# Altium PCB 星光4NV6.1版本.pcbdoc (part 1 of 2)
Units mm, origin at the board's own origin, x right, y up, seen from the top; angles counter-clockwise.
Board outline 96.4 x 47 mm, 2 copper layers (Top Layer, Bottom Layer), stack 1.58 mm thick; 27 components, 21 nets, 135 pads, 175 vias.
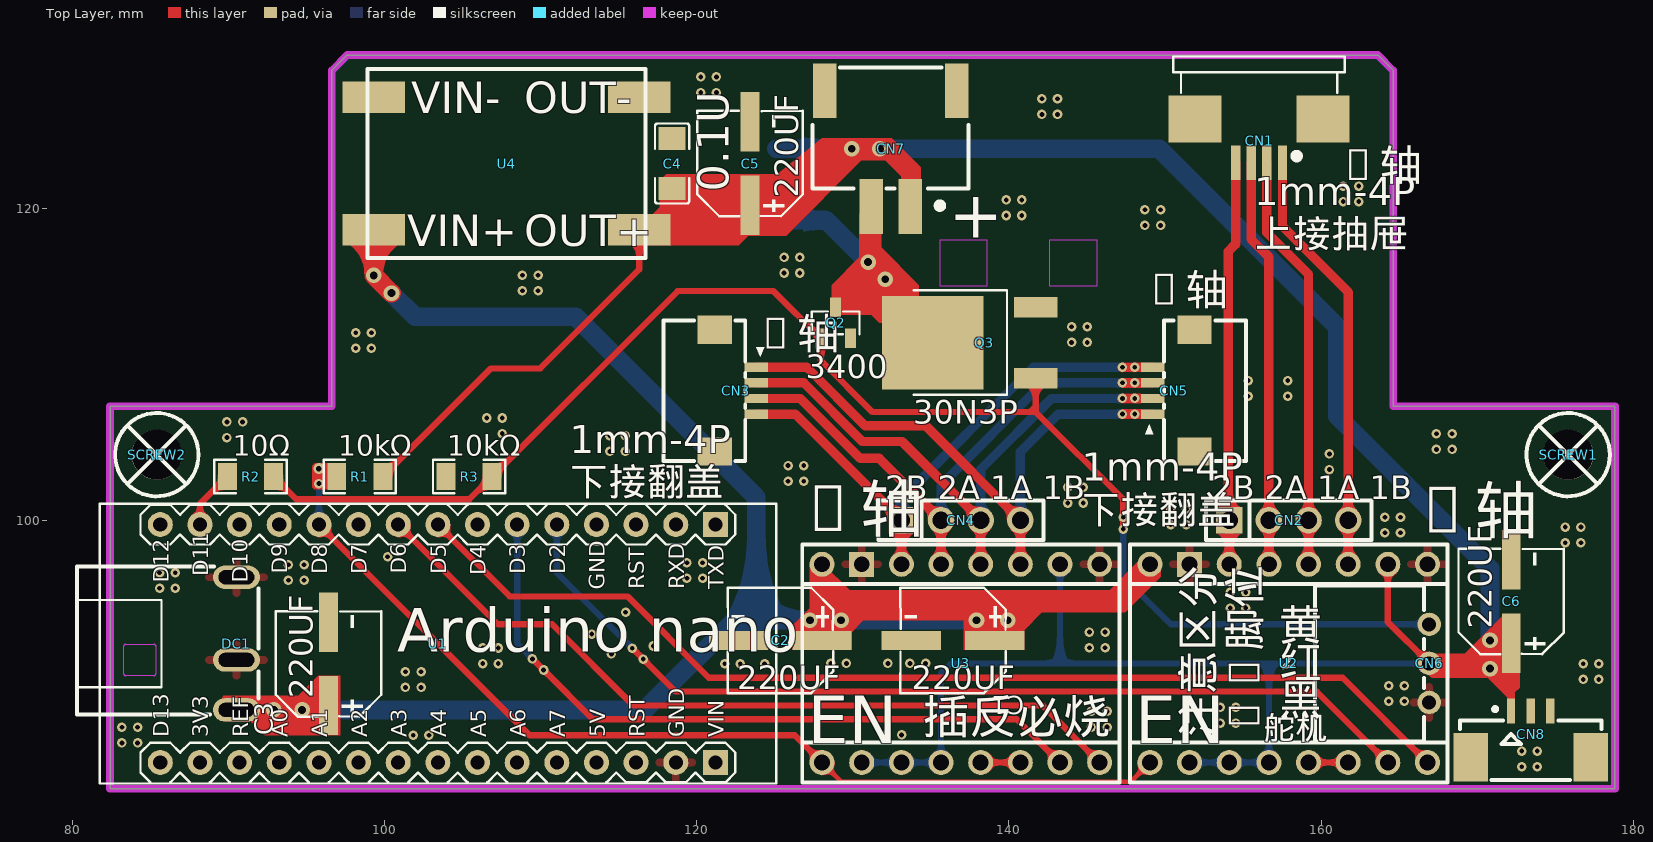
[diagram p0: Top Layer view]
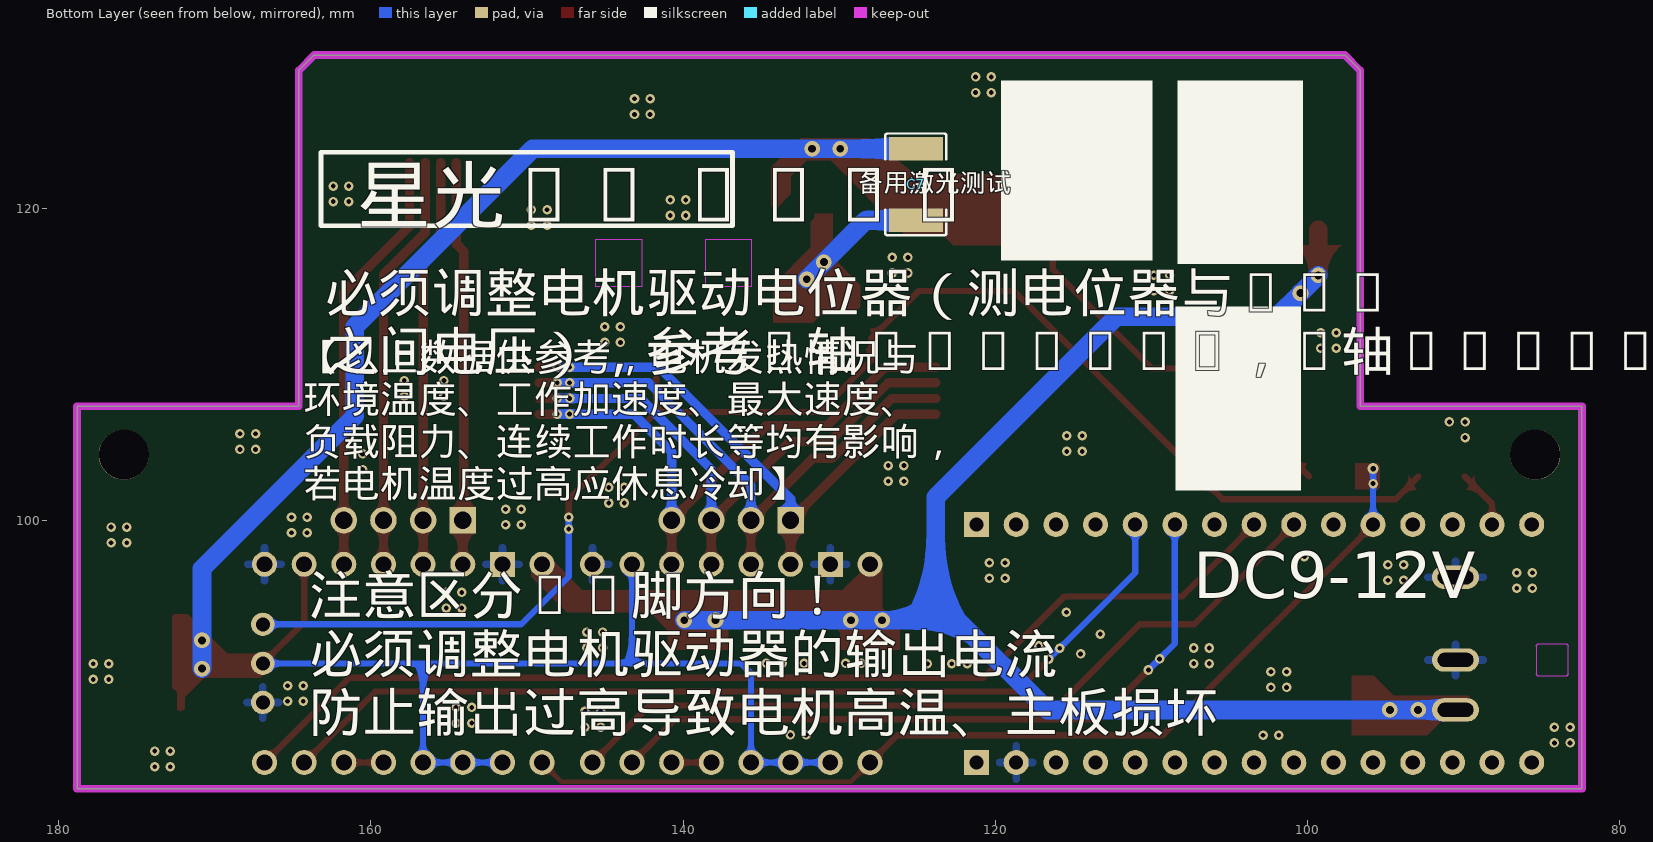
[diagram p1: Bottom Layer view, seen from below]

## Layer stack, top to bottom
Top Solder Mask Layer: solder mask 0.01, Dk 3.3
Top Layer: signal copper 0.035
Dielectric1: surface 1.51, FR4, Dk 4.5
Bottom Layer: signal copper 0.035
Bottom Solder Mask Layer: solder mask 0.01, Dk 3.3

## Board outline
97.623,129.804 163.623,129.804 164.623,128.804 164.623,107.304 164.623,114.304 164.623,107.304 178.823,107.304 178.823,82.804 82.423,82.804 82.423,107.304 96.623,107.304 96.623,128.804

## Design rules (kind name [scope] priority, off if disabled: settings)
BoardOutlineClearance copperThickness1oz [All] p0: genericclearance=0.254 ignorepadtopadclearanceinfootprint=FALSE except(0: Arc-SplitContinuation Track-SplitContinuation SMDPad-SplitContinuation THPad-SplitContinuation Via-SplitContinuation Fill-SplitContinuation Poly-SplitContinuation Region-SplitContinuation Text-SplitContinuation)
BoardOutlineClearance copperThickness2oz [All] p0: genericclearance=0.254 ignorepadtopadclearanceinfootprint=FALSE except(0: Arc-SplitContinuation Track-SplitContinuation SMDPad-SplitContinuation THPad-SplitContinuation Via-SplitContinuation Fill-SplitContinuation Poly-SplitContinuation Region-SplitContinuation Text-SplitContinuation)
BoardOutlineClearance Plane_innerPlane [All] p0: genericclearance=0.254 ignorepadtopadclearanceinfootprint=FALSE except(0: Arc-SplitContinuation Track-SplitContinuation SMDPad-SplitContinuation THPad-SplitContinuation Via-SplitContinuation Fill-SplitContinuation Poly-SplitContinuation Region-SplitContinuation Text-SplitContinuation)
BoardOutlineClearance Copper_copperRegion [All] p0: genericclearance=0.254 ignorepadtopadclearanceinfootprint=FALSE except(0: Arc-SplitContinuation Track-SplitContinuation SMDPad-SplitContinuation THPad-SplitContinuation Via-SplitContinuation Fill-SplitContinuation Poly-SplitContinuation Region-SplitContinuation Text-SplitContinuation)
BoardOutlineClearance Copper_copperRegion1 [All] p0: genericclearance=0.254 ignorepadtopadclearanceinfootprint=FALSE except(0: Arc-SplitContinuation Track-SplitContinuation SMDPad-SplitContinuation THPad-SplitContinuation Via-SplitContinuation Fill-SplitContinuation Poly-SplitContinuation Region-SplitContinuation Text-SplitContinuation)
BoardOutlineClearance otherClearance [All] p0: genericclearance=0.254 ignorepadtopadclearanceinfootprint=FALSE except(0: Arc-SplitContinuation Track-SplitContinuation SMDPad-SplitContinuation THPad-SplitContinuation Via-SplitContinuation Fill-SplitContinuation Poly-SplitContinuation Region-SplitContinuation Text-SplitContinuation)
Clearance copperThickness1oz [All] p1: gap=0.178 ignorepadtopadclearanceinfootprint=FALSE
Clearance copperThickness2oz [All] p1: gap=0.178 ignorepadtopadclearanceinfootprint=FALSE
Clearance Plane_innerPlane [All] p1: gap=0.178 ignorepadtopadclearanceinfootprint=FALSE
Clearance Copper_copperRegion [All] p1: gap=0.178 ignorepadtopadclearanceinfootprint=FALSE
Clearance Copper_copperRegion1 [All] p1: gap=0.178 ignorepadtopadclearanceinfootprint=FALSE
Clearance otherClearance [All] p1: gap=0.178 ignorepadtopadclearanceinfootprint=FALSE
DiffPairsRouting differentialPair [All] p1: maxuncoupledlength=10 minlimit=5.9843 maxlimit=Infinity mostfreqgap=5.9843 toplayer_minwidth=5 toplayer_prefwidth=10 toplayer_maxwidth=100 bottomlayer_minwidth=5 bottomlayer_prefwidth=10 bottomlayer_maxwidth=100
PasteMaskExpansion pasteMaskExpansion [All] p1: expansion=0
PlaneConnect innerPlane [All] p1: planeconnectstyle=Relief reliefexpansion=0.508 reliefentries=4 reliefconductorwidth=0.254 reliefairgap=0.254
PolygonConnect copperRegion [All] p1: connectstyle=Relief reliefentries=4 reliefconductorwidth=10 polygonreliefangle="90 Angle" airgapwidth=10
PolygonConnect copperRegion1 [All] p1: connectstyle=Relief reliefentries=4 reliefconductorwidth=19.685 polygonreliefangle="90 Angle" airgapwidth=10
RoutingVias viaSize [All] p1: viastyle="Through Hole" holewidth=12.0078 minholewidth=11.811 maxholewidth=248.0314 width=12.0078 minwidth=11.811 maxwidth=248.0314
SolderMaskExpansion solderMaskExpansion [All] p1: useseparateexpansions=TRUE expansion=2.0079 expansionbottom=2.0079
Width copperThickness1oz [All] p1: maxlimit=100 minlimit=5 preferedwidth=20
Width copperThickness2oz [All] p1: maxlimit=100 minlimit=5 preferedwidth=10

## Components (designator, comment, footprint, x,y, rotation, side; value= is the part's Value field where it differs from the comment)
C1 "" CAP-SMD_BD6.3-L6.6-W6.6-FD-1 136.423,92.304 r180 top locked
C2 "" CAP-SMD_BD6.3-L6.6-W6.6-FD-1 125.363,92.304 r180 top locked
C3 "" CAP-SMD_BD6.3-L6.6-W6.6-FD-1 96.423,90.804 r90 top locked
C4 "100nF" C1206 118.423,122.854 r270 top locked
C5 "" CAP-SMD_BD6.3-L6.6-W6.6-FD-1 123.423,122.854 r90 top locked
C6 "" CAP-SMD_BD6.3-L6.6-W6.6-FD-1 172.173,94.804 r90 top locked
C7 "" C1812 125.095,121.511 r90 bottom locked
CN1 "" FPC-SMD_4P-P1.00_AFA07-S04ECC-00 156.023,124.304 r180 top locked
CN2 "" HDR-TH_4P-P2.54-V-F 157.923,100.004 r0 top locked
CN3 "" FPC-SMD_4P-P1.00_10A20L04P 122.423,108.304 r270 top locked
CN4 "" HDR-TH_4P-P2.54-V-F 136.923,100.004 r0 top locked
CN5 "" FPC-SMD_4P-P1.00_10A20L04P 150.623,108.304 r90 top locked
CN6 "" HDR-TH_3P-P2.50_ZX-XH2.54-3PWZ 166.923,90.834 r270 top locked
CN7 "" CONN-SMD_2P-P2.54_MEGASTAR_ZX-XH2.54-2PWT 132.423,123.804 r180 top locked
CN8 "" CONN-SMD_1.25-3P 173.423,86.304 r0 top locked
DC1 "" DC-IN-TH_DC044 90.523,92.104 r0 top locked
Q2 "" SOT-23-3_L2.9-W1.3-P1.90-LS2.4-BR 128.905,112.649 r270 top locked
Q3 "" TO-252-2_L6.6-W6.1-P4.57-LS9.9-TL-CW 138.423,111.379 r180 top locked
R1 "10kΩ" R1206 98.423,102.804 r0 top locked
R2 "10Ω" R1206 91.423,102.804 r180 top locked
R3 "10kΩ" R1206 105.423,102.804 r0 top locked
SCREW1 "" M3螺丝 175.823,104.204 r0 top locked
SCREW2 "" M3螺丝 85.423,104.204 r0 top locked
U1 "" COMM-TH_ARDUINO_NANO 103.423,92.104 r0 top locked
U2 "" DIP-16_L20.3-W15.2-P2.54_LS12.7_A4988 157.923,90.834 r90 top locked
U3 "" DIP-16_L20.3-W15.2-P2.54_LS12.7_A4988 136.923,90.834 r90 top locked
U4 "" 迷你稳压模块 98.923,116.804 r0 top locked

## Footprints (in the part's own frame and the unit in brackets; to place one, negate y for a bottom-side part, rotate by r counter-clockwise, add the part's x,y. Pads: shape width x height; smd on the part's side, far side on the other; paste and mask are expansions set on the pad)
C1206 [mm]
  rect 1.485x1.728 smd: 1(-1.593,0) 2(1.593,0)
  silkscreen extent -2.56,-1.09 2.56,1.09
C1812 [mm]
  rect 1.485x3.456 smd: 1(-2.293,0) 2(2.293,0)
  silkscreen extent -3.26,-1.96 3.26,1.96
CAP-SMD_BD6.3-L6.6-W6.6-FD-1 [mm]
  rect 3.8x1.2 smd: 1(-2.67,0) 2(2.67,0)
  silkscreen extent -3.38,-3.38 3.38,3.38
COMM-TH_ARDUINO_NANO [mm]
  rect 1.6x1.6 hole 0.9: 1(17.78,7.62) 30(17.78,-7.62)
  round 1.6 hole 0.9: 2(15.24,7.62) 4(10.16,7.62) 6(5.08,7.62) 8(0,7.62) 10(-5.08,7.62) 12(-10.16,7.62) 14(-15.24,7.62) 15(-17.78,7.62) 16(-17.78,-7.62) 18(-12.7,-7.62) 20(-7.62,-7.62) 22(-2.54,-7.62) 24(2.54,-7.62) 26(7.62,-7.62) 28(12.7,-7.62) 29(15.24,-7.62)
  round 1.6 hole 0.9 copper offset 0,0: 3(12.7,7.62)
  round 1.6 hole 0.9 copper offset -0.001,0: 5(7.621,7.62) 7(2.541,7.62) 9(-2.539,7.62) 11(-7.619,7.62) 13(-12.699,7.62)
  round 1.6 hole 0.9 copper offset 0.001,0: 17(-15.241,-7.62) 19(-10.161,-7.62) 21(-5.081,-7.62) 23(-0.001,-7.62) 25(5.079,-7.62) 27(10.159,-7.62)
  silkscreen extent -23.11,-8.97 21.67,8.97
CONN-SMD_1.25-3P [mm]
  rect 0.52x1.6 smd: 1(-1.25,1.475) 2(0,1.475) 3(1.25,1.475)
  rect 2.2x3.1 smd: 4(3.85,-1.475) 5(-3.85,-1.475)
  silkscreen extent -4.52,-2.92 4.53,1.73
CONN-SMD_2P-P2.54_MEGASTAR_ZX-XH2.54-2PWT [mm]
  rect 1.5x3.5 smd: 1(-1.25,3.7) 2(1.25,3.7) 3(-4.23,-3.7) 4(4.23,-3.7)
  silkscreen extent -5,-5.21 5,3.85
DC-IN-TH_DC044 [mm]
  oval 3x1.5 hole 0.9 slot 2.3 at 0 deg: 2(0,4.25) 3(0,-1.05) 4(0,-4.25)
  Board Outline Layer lines w0.003: -7.209,-1.939 -7.209,-0.161 cw(c-7.082,-0.161) -7.082,-0.034 -5.304,-0.034 cw(c-5.304,-0.161) -5.177,-0.161 -5.177,-1.939 cw(c-5.304,-1.939) -5.304,-2.066 -7.082,-2.066 cw(c-7.082,-1.939) -7.209,-1.939
  Board Outline Layer region: -7.209,-1.939 -7.209,-0.161 -7.199,-0.112 -7.172,-0.071 -7.131,-0.044 -7.082,-0.034 -7.082,-0.034 -5.304,-0.034 -5.255,-0.044 -5.214,-0.071 -5.187,-0.112 -5.177,-0.161 -5.177,-0.161 -5.177,-1.939 -5.187,-1.988 -5.214,-2.029 -5.255,-2.056 -5.304,-2.066 -5.304,-2.066 -7.082,-2.066 -7.131,-2.056 -7.172,-2.029 -7.199,-1.988 -7.209,-1.939
  Board Outline Layer region: -7.209,-1.939 -7.209,-0.161 -7.199,-0.112 -7.172,-0.071 -7.131,-0.044 -7.082,-0.034 -7.082,-0.034 -5.304,-0.034 -5.255,-0.044 -5.214,-0.071 -5.187,-0.112 -5.177,-0.161 -5.177,-0.161 -5.177,-1.939 -5.187,-1.988 -5.214,-2.029 -5.255,-2.056 -5.304,-2.066 -5.304,-2.066 -7.082,-2.066 -7.131,-2.056 -7.172,-2.029 -7.199,-1.988 -7.209,-1.939
  silkscreen extent -10.2,-4.55 1.4,4.95
DIP-16_L20.3-W15.2-P2.54_LS12.7_A4988 [mm]
  round 1.6 hole 1.02: 1(-6.35,8.89) 2(-6.35,6.35) 3(-6.35,3.81) 4(-6.35,1.27) 5(-6.35,-1.27) 6(-6.35,-3.81) 7(-6.35,-6.35) 8(-6.35,-8.89) 9(6.35,-8.89) 10(6.35,-6.35) 11(6.35,-3.81) 12(6.35,-1.27) 13(6.35,1.27) 14(6.35,3.81) 16(6.35,8.89)
  rect 1.6x1.6 hole 1.02: 15(6.35,6.35)
  silkscreen extent -7.62,-10.16 7.62,10.16
FPC-SMD_4P-P1.00_10A20L04P [mm]
  rect 0.6x1.5 smd: 1(-1.5,1.4) 2(-0.5,1.4) 3(0.5,1.4) 4(1.5,1.4)
  rect 1.8x2.2 smd: 5(3.9,-1.263) 6(-3.9,-1.263)
  silkscreen extent -4.5,-4.56 4.5,1.9
FPC-SMD_4P-P1.00_AFA07-S04ECC-00 [mm]
  rect 0.6x2.2 smd: 1(-1.5,1.4) 2(-0.5,1.4) 3(0.5,1.4) 4(1.5,1.4)
  rect 3.4x3 smd: 5(4.1,-1.4) 6(-4.1,-1.4)
  silkscreen extent -5.5,-5.4 5.5,1.17
HDR-TH_3P-P2.50_ZX-XH2.54-3PWZ [mm]
  round 1.5 hole 0.9: 1(-2.5,0) 2(0,0) 3(2.5,0)
  silkscreen extent -5,-7.32 5,-0.32
HDR-TH_4P-P2.54-V-F [mm]
  rect 1.7x1.7 hole 1.1: 1(-3.81,0)
  round 1.7 hole 1.1: 2(-1.27,0) 3(1.27,0) 4(3.81,0)
  silkscreen extent -5.29,-1.27 5.29,1.27
M3螺丝 [mil]
  round 126 hole 126: 1(0,0)
  silkscreen extent -105,-105 105,105
R1206 [mm]
  rect 1.208x1.701 smd: 1(-1.479,0) 2(1.479,0)
  silkscreen extent -2.31,-1.08 2.31,1.08
SOT-23-3_L2.9-W1.3-P1.90-LS2.4-BR [mm]
  rect 1.25x0.7 smd: 1(1,-0.95) 2(1,0.95) 3(-1,0)
  silkscreen extent -0.73,-1.53 0.73,1.53
TO-252-2_L6.6-W6.1-P4.57-LS9.9-TL-CW [mm]
  rect 2.8x1.3 smd: 1(-3.292,2.273) 3(-3.292,-2.273)
  rect 6.5x6 smd: 2(3.292,0)
  silkscreen extent -1.46,-3.35 4.51,3.34
迷你稳压模块 [mm]
  rect 4x2 smd: 1(0.4,10.3) 2(0.4,1.8) 3(17.4,10.3) 4(17.4,1.8)
  silkscreen extent 0,0 17.8,12.1

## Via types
v1: diameter 0.61, hole 0.305, Top Layer to Bottom Layer, 160 vias
v2: diameter 1, hole 0.5, Top Layer to Bottom Layer, 14 vias
v3: diameter 0.7, hole 0.35, Top Layer to Bottom Layer, 1 vias

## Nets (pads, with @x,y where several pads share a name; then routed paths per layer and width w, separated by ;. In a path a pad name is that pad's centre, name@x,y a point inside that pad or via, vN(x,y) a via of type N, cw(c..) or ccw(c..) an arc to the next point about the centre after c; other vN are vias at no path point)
5V: C4.2 C5.1 C6.1 C7.2 CN6.2 CN7.1 CN8.1 R1.2 U2.2 U2.3 U2.4 U2.10 U3.2 U3.3 U3.4 U3.10 U4.4 | length 160
  Top Layer w0.4: R1.2@99.902,102.804 106.826,109.728 109.982,109.728 116.323,116.069 U4.4@116.323,118.604 ; U2.10@164.273,97.184 164.273,93.484 CN6.2@166.923,90.834
  Bottom Layer w0.4: U3.2@130.573,84.484 U3.3@133.113,84.484 U3.4@135.653,84.484 135.653,90.187 136.3,90.834 142.886,90.834 ; U3.10@143.273,97.184 143.273,91.221 ; U2.2@151.573,84.484 U2.3@154.113,84.484 U2.4@156.653,84.484 156.653,90.458 ; CN6.2@166.923,90.834 157.029,90.834 ; 142.886,90.834 143.273,91.221 ; 142.886,90.834 143.66,90.834 ; 143.273,91.221 143.66,90.834 ; 143.66,90.834 156.277,90.834 ; 156.277,90.834 156.653,90.458 ; 156.277,90.834 157.029,90.834 ; 156.653,90.458 157.029,90.834
  Bottom Layer w1.2: C7.2@125.095,123.804 v2(129.936,123.804) v2(131.739,123.804) 149.627,123.804 161.036,112.395 161.036,106.68 170.815,96.901 v2(170.815,92.304) v2(170.815,90.501)
12V: C1.1 C2.1 C3.1 DC1.4 U2.16 U3.16 U4.2 | length 97.1
  Top Layer w1.2: U4.2@99.323,118.604 v2(99.323,115.688) v2(100.457,114.554)
  Bottom Layer w1.2: DC1.4@90.523,87.854 v2(94.726,87.854) 116.683,87.854 122.428,93.599 ; v2(99.323,115.688) v2(100.457,114.554) 101.981,113.03 112.268,113.03 123.825,101.473 123.825,94.996 ; v2(139.923,93.599) v2(137.923,93.599) v2(129.254,93.599) v2(127.254,93.599) 125.222,93.599 ; 122.428,93.599 123.825,94.996 ; 122.428,93.599 125.222,93.599 ; 123.825,94.996 125.222,93.599
  other v2: 92.923,87.854
$1N38281: U3.5 U3.6 | length 2.5
  Top Layer w0.4: U3.5@138.193,84.484 U3.6@140.733,84.484
$1N38618: CN3.1 CN4.4 CN5.1 U3.11 | length 38.5
  Top Layer w0.6: CN3.1@123.823,109.804 127.051,109.804 130.806,106.049 134.688,106.049 CN4.4@140.733,100.004 U3.11@140.733,97.184 ; v1(147.268,106.804) v1(148.067,106.804) CN5.1@149.223,106.804
  Bottom Layer w0.6: CN4.4@140.733,100.004 140.733,104.373 143.164,106.804 v1(147.268,106.804) v1(148.067,106.804)
$1N38619: CN3.2 CN4.3 CN5.2 U3.12 | length 37.8
  Top Layer w0.6: CN3.2@123.823,108.804 126.853,108.804 130.609,105.048 133.149,105.048 CN4.3@138.193,100.004 U3.12@138.193,97.184 ; v1(147.268,107.804) v1(148.067,107.804) CN5.2@149.223,107.804
  Bottom Layer w0.6: CN4.3@138.193,100.004 138.193,103.268 142.729,107.804 v1(147.268,107.804) v1(148.067,107.804)
$1N38620: CN3.3 CN4.2 CN5.3 U3.13 | length 37.2
  Top Layer w0.6: CN3.3@123.823,107.804 126.638,107.804 130.475,103.967 131.69,103.967 CN4.2@135.653,100.004 U3.13@135.653,97.184 ; v1(147.268,108.804) v1(148.067,108.804) CN5.3@149.223,108.804
  Bottom Layer w0.6: CN4.2@135.653,100.004 135.653,102.252 142.205,108.804 v1(147.268,108.804) v1(148.067,108.804)
$1N38622: CN3.4 CN4.1 CN5.4 U3.14 | length 36.7
  Top Layer w0.6: CN3.4@123.823,106.804 126.313,106.804 CN4.1@133.113,100.004 U3.14@133.113,97.184 ; v1(147.268,109.804) v1(148.067,109.804) CN5.4@149.223,109.804
  Bottom Layer w0.6: CN4.1@133.113,100.004 133.113,101.363 141.554,109.804 v1(147.268,109.804) v1(148.067,109.804)
$1N39292: U2.5 U2.6 | length 2.5
  Top Layer w0.4: U2.5@159.193,84.484 U2.6@161.733,84.484
$1N39467: CN1.1 CN2.4 U2.11 | length 27.5
  Top Layer w0.6: CN1.1@157.523,122.904 157.523,118.829 161.733,114.619 CN2.4@161.733,100.004 U2.11@161.733,97.184
$1N39468: CN1.2 CN2.3 U2.12 | length 26.8
  Top Layer w0.6: CN1.2@156.523,122.904 156.523,118.432 159.193,115.762 CN2.3@159.193,100.004 U2.12@159.193,97.184
$1N39469: CN1.4 CN2.1 U2.14 | length 25.9
  Top Layer w0.6: U2.14@154.113,97.184 CN2.1@154.113,100.004 154.051,100.066 154.051,117.221 154.523,117.693 CN1.4@154.523,122.904
$1N39470: CN1.3 CN2.2 U2.13 | length 26.2
  Top Layer w0.6: CN1.3@155.523,122.904 155.523,117.994 156.653,116.864 CN2.2@156.653,100.004 U2.13@156.653,97.184
$1N40367: C7.1 CN7.2 Q2.3 Q3.2 | length 8.5
  Bottom Layer w1.2: C7.1@125.095,119.219 128.304,119.219 v2(130.982,116.541) v2(132.08,115.443)
$1N40669: CN6.1 Q2.1 Q3.1 R2.1 R3.2 | length 96.2
  Top Layer w0.4: R2.1@92.902,102.804 94.36,101.346 105.444,101.346 R3.2@106.902,102.804 118.779,114.681 124.923,114.681 Q2.1@127.955,111.649 127.955,110.242 131.263,106.934 141.338,106.934 ; Q3.1@141.715,109.106 141.715,107.311 ; v1(147.32,99.441) v1(147.32,100.195) 147.32,101.346 141.732,106.934 ; 141.338,106.934 141.715,107.311 ; 141.338,106.934 141.732,106.934 ; 141.715,107.311 141.715,106.951 141.732,106.934
  Bottom Layer w0.4: v1(147.32,100.195) v1(147.32,99.441) 147.32,96.393 150.379,93.334 CN6.1@166.923,93.334
D2/X-STEP: U1.5 U2.7 | length 62.3
  Top Layer w0.4: v1(115.881,91.81) v1(116.582,91.11) 118.665,89.027 159.73,89.027 U2.7@164.273,84.484
  Bottom Layer w0.4: U1.5@111.044,99.724 111.043,96.649 v1(115.881,91.81) v1(116.582,91.11)
D3/Y-STEP: U1.6 U3.7 | length 46.6
  Top Layer w0.4: v1(109.483,91.124) v1(110.196,90.411) 113.358,87.249 140.508,87.249 U3.7@143.273,84.484
  Bottom Layer w0.4: U1.6@108.503,99.724 108.503,92.104 v1(109.483,91.124) v1(110.196,90.411)
D5/X-DIR: U1.8 U2.8 | length 69.7
  Top Layer w0.4: U1.8@103.423,99.724 108.024,95.123 115.57,95.123 120.777,89.916 161.381,89.916 U2.8@166.813,84.484
D6/Y-DIR: U1.9 U3.8 | length 51.2
  Top Layer w0.4: U1.9@100.884,99.724 107.262,93.345 110.744,93.345 115.951,88.138 142.159,88.138 U3.8@145.813,84.484
D8/EN: R1.1 U1.11 U2.1 U3.1 | length 64.1
  Top Layer w0.3: U3.1@128.033,84.484 129.263,83.254 147.803,83.254 U2.1@149.033,84.484
  Top Layer w0.4: U1.11@95.804,99.724 109.294,86.233 126.284,86.233 U3.1@128.033,84.484
  Bottom Layer w0.4: U1.11@95.804,99.724 v1(95.803,102.35) v3(95.803,103.312)
D11/PWM: R2.2 U1.14 | length 3.8
  Top Layer w0.4: U1.14@88.183,99.724 88.183,101.043 R2.2@89.944,102.804
GND: C1.2 C2.2 C3.2 C4.1 C5.2 C6.2 CN1.5 CN1.6 CN3.5 CN3.6 CN5.5 CN5.6 CN6.3 CN7.3 CN7.4 CN8.3 CN8.4 CN8.5 DC1.2 DC1.3 Q2.2 Q3.3 R3.1 U1.29 U2.9 U2.15 U3.9 U3.15 U4.1 U4.3
  other v1: 172.847,84.217 173.847,84.217 172.847,85.217 173.847,85.217 83.185,85.741 84.185,85.741 101.854,86.233 102.854,86.233 132.123,86.249 133.123,86.249 83.185,86.741 84.185,86.741 145.288,86.757 146.288,86.757 153.543,87.011 154.543,87.011 145.288,87.757 146.288,87.757 153.543,88.011 154.543,88.011 164.338,88.408 165.338,88.408 101.346,89.297 102.346,89.297 164.338,89.408 165.338,89.408 176.784,89.805 177.784,89.805 101.346,90.297 102.346,90.297 121.793,90.805 122.793,90.805 124.346,90.805 176.784,90.805 177.784,90.805 106.299,90.821 107.299,90.821 128.594,90.834 129.594,90.834 132.25,90.834 133.662,90.834 134.662,90.834 114.538,91.44 106.299,91.821 107.299,91.821 145.161,91.837 146.161,91.837 117.221,91.948 113.284,92.71 145.161,92.837 146.161,92.837 115.443,94.107 154.178,94.377 155.178,94.377 154.178,95.377 155.178,95.377 85.598,95.647 86.598,95.647 93.853,96.155 94.853,96.155 119.38,96.282 120.38,96.282 85.598,96.647 86.598,96.647 93.853,97.155 94.853,97.155 119.38,97.282 120.38,97.282 100.203,97.663 175.641,98.568 176.641,98.568 164.084,99.203 165.084,99.203 175.641,99.568 176.641,99.568 150.368,99.711 151.368,99.711 164.084,100.203 165.084,100.203 150.368,100.711 151.368,100.711 143.764,101.108 144.764,101.108 143.764,102.108 144.764,102.108 125.857,102.505 126.857,102.505 160.528,103.251 125.857,103.505 126.857,103.505 160.528,104.251 114.427,104.41 115.427,104.41 167.386,104.537 168.386,104.537 89.916,105.299 114.427,105.41 115.427,105.41 167.386,105.537 168.386,105.537 107.553,105.553 89.916,106.299 90.916,106.299 106.553,106.553 107.553,106.553 155.321,107.95 157.861,107.95 155.321,108.95 157.861,108.95 98.171,111.014 99.171,111.014 144.018,111.395 145.018,111.395 98.171,112.014 99.171,112.014 144.018,112.395 145.018,112.395 108.839,114.697 109.839,114.697 108.839,115.697 109.839,115.697 125.603,115.84 126.603,115.84 125.603,116.84 126.603,116.84 148.717,118.888 149.717,118.888 139.827,119.523 140.827,119.523 148.717,119.888 149.717,119.888 161.417,120.412 162.417,120.412 139.827,120.523 140.827,120.523 161.417,121.412 162.417,121.412 142.113,126 143.113,126 142.113,127 143.113,127 120.269,127.397 121.269,127.397 120.269,128.397 121.269,128.397
pads on no net: CN8.2 SCREW1.1 SCREW2.1 U1.1 U1.2 U1.3 U1.4 U1.7 U1.10 U1.12 U1.13 U1.15 U1.16 U1.17 U1.18 U1.19 U1.20 U1.21 U1.22 U1.23 U1.24 U1.25 U1.26 U1.27 U1.28 U1.30

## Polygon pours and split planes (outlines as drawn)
GND on Top Layer (solid, remove dead copper, pour order 0): 78.74,135.89 185.547,135.89 185.547,76.2 78.74,76.2
GND on Bottom Layer (solid, remove dead copper, pour order 2): 76.2,134.62 186.182,134.62 186.182,77.343 76.2,77.343

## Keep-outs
Board Outline Layer:
  region: 135.597,117.983 138.597,117.983 138.597,114.983 135.597,114.983
  region: 135.597,117.983 138.597,117.983 138.597,114.983 135.597,114.983
  region: 142.623,117.983 145.623,117.983 145.623,114.983 142.623,114.983
  region: 142.623,117.983 145.623,117.983 145.623,114.983 142.623,114.983
  lines w0.003: 135.597,114.983 138.597,114.983 138.597,117.983 135.597,117.983 135.597,114.983 ; 142.623,114.983 145.623,114.983 145.623,117.983 142.623,117.983 142.623,114.983
  lines w0.5: 164.623,107.304 164.623,128.804 163.623,129.804 97.623,129.804 96.623,128.804 96.623,107.304 82.423,107.304 82.423,82.804 178.823,82.804 178.823,107.304 164.623,107.304 ; 164.623,107.304 164.623,114.304 164.623,107.304

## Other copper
Top Layer:
  region net 12V: 127.254,97.155 127.254,94.374 126.111,93.231 126.111,91.694 129.921,91.694 129.921,92.837 130.683,93.599 137.106,93.599 137.106,91.694 140.97,91.694 140.97,92.964 142.113,94.107 147.447,94.107 149.733,96.393 149.733,97.389 148.286,97.389 146.458,95.504 129.794,95.504 128.143,97.155
  region net 12V: 89.535,88.519 89.663,88.773 94.488,88.773 95.758,90.043 97.155,90.043 97.155,86.233 92.329,86.233 91.44,87.122 89.789,87.122 89.535,87.376
  region net 5V: 115.487,119.507 117.094,119.507 117.623,120.036 117.623,121.754 118.043,122.174 125.153,122.174 128.024,124.46 132.488,124.46 134.366,122.63 134.366,120.142 134.112,119.888 133.096,120.904 133.096,122.047 132.08,123.063 130.556,123.063 125.73,118.237 123.317,118.237 122.682,117.602 116.332,117.602 116.332,118.662
  region net $1N40367: 130.429,119.634 130.429,116.84 128.651,115.062 128.651,113.665 129.159,113.157 131.191,113.157 131.699,112.649 134.239,112.649 134.239,115.062 131.826,117.475 131.826,119.126 131.572,119.38 131.572,119.634
  region net 5V: 169.19,91.44 171.73,93.98 172.593,93.98 172.72,93.853 172.72,89.281 172.414,88.975 172.414,87.865 172.173,87.779 171.929,87.928 171.929,88.675 170.688,89.916 167.092,89.916 166.497,90.369 166.497,91.44
  region net D8/EN: 96.944,103.654 95.538,103.654 95.377,103.493 95.377,102.108 95.504,101.981 96.944,101.981
  region net D8/EN: 96.715,99.095 96.432,98.812 96.392,98.849 96.354,98.878 96.316,98.901 96.278,98.918 96.24,98.93 96.203,98.937 96.125,98.942 96.044,98.938 95.956,98.93 95.86,98.924 95.753,98.926 96.601,99.774 96.603,99.667 96.597,99.571 96.589,99.483 96.585,99.402 96.59,99.324 96.597,99.287 96.609,99.249 96.626,99.211 96.649,99.173 96.678,99.135
  region net D6/Y-DIR: 101.795,99.095 101.512,98.812 101.472,98.849 101.434,98.878 101.396,98.901 101.358,98.918 101.32,98.93 101.283,98.937 101.205,98.942 101.124,98.938 101.036,98.93 100.94,98.924 100.833,98.926 101.681,99.774 101.683,99.667 101.677,99.571 101.669,99.483 101.665,99.402 101.67,99.324 101.677,99.287 101.689,99.249 101.706,99.211 101.729,99.173 101.758,99.135
  region net D5/X-DIR: 104.335,99.095 104.052,98.812 104.012,98.849 103.974,98.878 103.936,98.901 103.898,98.918 103.86,98.93 103.823,98.937 103.745,98.942 103.664,98.938 103.576,98.93 103.48,98.924 103.373,98.926 104.221,99.774 104.223,99.667 104.217,99.571 104.209,99.483 104.205,99.402 104.21,99.324 104.217,99.287 104.229,99.249 104.246,99.211 104.269,99.173 104.298,99.135
  region net D11/PWM: 87.983,100.813 88.383,100.813 88.385,100.76 88.392,100.712 88.403,100.669 88.417,100.63 88.435,100.595 88.457,100.563 88.508,100.505 88.569,100.45 88.636,100.394 88.708,100.33 88.783,100.253 87.583,100.253 87.658,100.33 87.73,100.394 87.797,100.45 87.858,100.505 87.909,100.563 87.931,100.595 87.949,100.63 87.963,100.669 87.974,100.712 87.981,100.76
  region net D5/X-DIR: 165.901,85.113 166.184,85.396 166.224,85.359 166.262,85.33 166.3,85.307 166.338,85.29 166.376,85.278 166.413,85.271 166.491,85.266 166.572,85.27 166.66,85.278 166.756,85.284 166.863,85.282 166.015,84.434 166.013,84.541 166.019,84.637 166.027,84.725 166.031,84.806 166.026,84.884 166.019,84.921 166.007,84.959 165.99,84.997 165.967,85.035 165.938,85.073
  region net D2/X-STEP: 163.361,85.113 163.644,85.396 163.684,85.359 163.722,85.33 163.76,85.307 163.798,85.29 163.836,85.278 163.873,85.271 163.951,85.266 164.032,85.27 164.12,85.278 164.216,85.284 164.323,85.282 163.475,84.434 163.473,84.541 163.479,84.637 163.487,84.725 163.491,84.806 163.486,84.884 163.479,84.921 163.467,84.959 163.45,84.997 163.427,85.035 163.398,85.073
  region net $1N39292: 160.644,84.284 160.644,84.684 160.697,84.686 160.745,84.693 160.788,84.704 160.827,84.718 160.862,84.736 160.894,84.758 160.952,84.809 161.007,84.87 161.063,84.937 161.127,85.009 161.204,85.084 161.204,83.884 161.127,83.959 161.063,84.031 161.007,84.098 160.952,84.159 160.894,84.21 160.862,84.232 160.827,84.25 160.788,84.264 160.745,84.275 160.697,84.282
  region net $1N39292: 160.282,84.684 160.282,84.284 160.229,84.282 160.181,84.275 160.138,84.264 160.099,84.25 160.064,84.232 160.032,84.21 159.974,84.159 159.919,84.098 159.863,84.031 159.799,83.959 159.722,83.884 159.722,85.084 159.799,85.009 159.863,84.937 159.919,84.87 159.974,84.809 160.032,84.758 160.064,84.736 160.099,84.718 160.138,84.704 160.181,84.693 160.229,84.686
  region net D8/EN: 148.369,83.608 148.157,83.82 148.197,83.864 148.228,83.906 148.251,83.946 148.267,83.985 148.277,84.024 148.281,84.062 148.278,84.14 148.264,84.222 148.247,84.313 148.235,84.416 148.233,84.473 148.235,84.534 149.083,83.686 149.022,83.684 148.965,83.686 148.862,83.698 148.771,83.715 148.689,83.729 148.611,83.732 148.573,83.728 148.534,83.718 148.495,83.702 148.455,83.679 148.413,83.648
  region net 5V: 164.473,96.095 164.073,96.095 164.071,96.148 164.064,96.196 164.053,96.239 164.039,96.278 164.021,96.313 163.999,96.345 163.948,96.403 163.887,96.458 163.82,96.514 163.748,96.578 163.673,96.655 164.873,96.655 164.798,96.578 164.726,96.514 164.659,96.458 164.598,96.403 164.547,96.345 164.525,96.313 164.507,96.278 164.493,96.239 164.482,96.196 164.475,96.148
  region net $1N39467: 161.433,98.273 162.033,98.273 162.04,98.191 162.059,98.114 162.088,98.041 162.127,97.972 162.172,97.905 162.223,97.841 162.333,97.713 161.133,97.713 161.243,97.841 161.294,97.905 161.339,97.972 161.378,98.041 161.407,98.114 161.426,98.191
  region net $1N39468: 158.893,98.273 159.493,98.273 159.5,98.191 159.519,98.114 159.548,98.041 159.587,97.972 159.632,97.905 159.683,97.841 159.793,97.713 158.593,97.713 158.703,97.841 158.754,97.905 158.799,97.972 158.838,98.041 158.867,98.114 158.886,98.191
  region net $1N39470: 156.353,98.273 156.953,98.273 156.96,98.191 156.979,98.114 157.008,98.041 157.047,97.972 157.092,97.905 157.143,97.841 157.253,97.713 156.053,97.713 156.163,97.841 156.214,97.905 156.259,97.972 156.298,98.041 156.327,98.114 156.346,98.191
  region net $1N39469: 153.813,98.273 154.413,98.273 154.42,98.191 154.439,98.114 154.468,98.041 154.507,97.972 154.552,97.905 154.603,97.841 154.713,97.713 153.513,97.713 153.623,97.841 153.674,97.905 153.719,97.972 153.758,98.041 153.787,98.114 153.806,98.191
  region net D6/Y-DIR: 144.901,85.113 145.184,85.396 145.224,85.359 145.262,85.33 145.3,85.307 145.338,85.29 145.376,85.278 145.413,85.271 145.491,85.266 145.572,85.27 145.66,85.278 145.756,85.284 145.863,85.282 145.015,84.434 145.013,84.541 145.019,84.637 145.027,84.725 145.031,84.806 145.026,84.884 145.019,84.921 145.007,84.959 144.99,84.997 144.967,85.035 144.938,85.073
  region net D3/Y-STEP: 142.361,85.113 142.644,85.396 142.684,85.359 142.722,85.33 142.76,85.307 142.798,85.29 142.836,85.278 142.873,85.271 142.951,85.266 143.032,85.27 143.12,85.278 143.216,85.284 143.323,85.282 142.475,84.434 142.473,84.541 142.479,84.637 142.487,84.725 142.491,84.806 142.486,84.884 142.479,84.921 142.467,84.959 142.45,84.997 142.427,85.035 142.398,85.073
  region net $1N38281: 139.644,84.284 139.644,84.684 139.697,84.686 139.745,84.693 139.788,84.704 139.827,84.718 139.862,84.736 139.894,84.758 139.952,84.809 140.007,84.87 140.063,84.937 140.127,85.009 140.204,85.084 140.204,83.884 140.127,83.959 140.063,84.031 140.007,84.098 139.952,84.159 139.894,84.21 139.862,84.232 139.827,84.25 139.788,84.264 139.745,84.275 139.697,84.282
  region net $1N38281: 139.282,84.684 139.282,84.284 139.229,84.282 139.181,84.275 139.138,84.264 139.099,84.25 139.064,84.232 139.032,84.21 138.974,84.159 138.919,84.098 138.863,84.031 138.799,83.959 138.722,83.884 138.722,85.084 138.799,85.009 138.863,84.937 138.919,84.87 138.974,84.809 139.032,84.758 139.064,84.736 139.099,84.718 139.138,84.704 139.181,84.693 139.229,84.686
  region net D8/EN: 128.909,83.82 128.697,83.608 128.653,83.648 128.611,83.679 128.571,83.702 128.532,83.718 128.493,83.728 128.455,83.732 128.377,83.729 128.295,83.715 128.204,83.698 128.101,83.686 128.044,83.684 127.983,83.686 128.831,84.534 128.833,84.473 128.831,84.416 128.819,84.313 128.802,84.222 128.788,84.14 128.785,84.062 128.789,84.024 128.799,83.985 128.815,83.946 128.838,83.906 128.869,83.864
  region net D8/EN: 127.121,85.113 127.404,85.396 127.444,85.359 127.482,85.33 127.52,85.307 127.558,85.29 127.596,85.278 127.633,85.271 127.711,85.266 127.792,85.27 127.88,85.278 127.976,85.284 128.083,85.282 127.235,84.434 127.233,84.541 127.239,84.637 127.247,84.725 127.251,84.806 127.246,84.884 127.239,84.921 127.227,84.959 127.21,84.997 127.187,85.035 127.158,85.073
  region net $1N38618: 140.433,98.273 141.033,98.273 141.04,98.191 141.059,98.114 141.088,98.041 141.127,97.972 141.172,97.905 141.223,97.841 141.333,97.713 140.133,97.713 140.243,97.841 140.294,97.905 140.339,97.972 140.378,98.041 140.407,98.114 140.426,98.191
  region net $1N38619: 137.893,98.273 138.493,98.273 138.5,98.191 138.519,98.114 138.548,98.041 138.587,97.972 138.632,97.905 138.683,97.841 138.793,97.713 137.593,97.713 137.703,97.841 137.754,97.905 137.799,97.972 137.838,98.041 137.867,98.114 137.886,98.191
  region net $1N38620: 135.353,98.273 135.953,98.273 135.96,98.191 135.979,98.114 136.008,98.041 136.047,97.972 136.092,97.905 136.143,97.841 136.253,97.713 135.053,97.713 135.163,97.841 135.214,97.905 135.259,97.972 135.298,98.041 135.327,98.114 135.346,98.191
  region net $1N38622: 132.813,98.273 133.413,98.273 133.42,98.191 133.439,98.114 133.468,98.041 133.507,97.972 133.552,97.905 133.603,97.841 133.713,97.713 132.513,97.713 132.623,97.841 132.674,97.905 132.719,97.972 132.758,98.041 132.787,98.114 132.806,98.191
  region net 5V: 166.06,91.415 166.342,91.698 166.378,91.665 166.414,91.638 166.449,91.616 166.484,91.6 166.519,91.589 166.554,91.581 166.626,91.574 166.702,91.575 166.784,91.581 166.872,91.585 166.97,91.583 166.174,90.787 166.173,90.885 166.177,90.973 166.182,91.055 166.183,91.131 166.177,91.203 166.169,91.238 166.157,91.273 166.141,91.308 166.119,91.343 166.093,91.379
  region net $1N39469: 154.413,98.254 153.813,98.254 ccw(c152.688,98.254) 153.363,99.154 154.863,99.154 ccw(c155.538,98.254)
  region net $1N39469: 153.751,101.754 154.351,101.754 ccw(c155.476,101.754) 154.801,100.854 153.301,100.854 ccw(c152.626,101.754)
  region net $1N39470: 156.953,98.847 156.353,98.847 156.351,98.893 156.345,98.938 156.324,99.02 156.291,99.097 156.248,99.168 156.196,99.237 156.139,99.304 156.016,99.442 157.291,99.442 157.167,99.304 157.11,99.237 157.058,99.168 157.015,99.097 156.982,99.02 156.961,98.938 156.955,98.893
  region net $1N39470: 156.353,101.161 156.953,101.161 156.955,101.115 156.961,101.07 156.982,100.988 157.015,100.911 157.058,100.84 157.11,100.771 157.167,100.704 157.291,100.566 156.016,100.566 156.139,100.704 156.196,100.771 156.248,100.84 156.291,100.911 156.324,100.988 156.345,101.07 156.351,101.115
  region net $1N39468: 159.493,98.847 158.893,98.847 158.891,98.893 158.885,98.938 158.864,99.02 158.831,99.097 158.788,99.168 158.736,99.237 158.679,99.304 158.556,99.442 159.831,99.442 159.707,99.304 159.65,99.237 159.598,99.168 159.555,99.097 159.522,99.02 159.501,98.938 159.495,98.893
  region net $1N39468: 158.893,101.161 159.493,101.161 159.495,101.115 159.501,101.07 159.522,100.988 159.555,100.911 159.598,100.84 159.65,100.771 159.707,100.704 159.831,100.566 158.556,100.566 158.679,100.704 158.736,100.771 158.788,100.84 158.831,100.911 158.864,100.988 158.885,101.07 158.891,101.115
  region net $1N39467: 162.033,98.847 161.433,98.847 161.431,98.893 161.425,98.938 161.404,99.02 161.371,99.097 161.328,99.168 161.276,99.237 161.219,99.304 161.096,99.442 162.371,99.442 162.247,99.304 162.19,99.237 162.138,99.168 162.095,99.097 162.062,99.02 162.041,98.938 162.035,98.893
  region net $1N39467: 161.433,101.161 162.033,101.161 162.035,101.115 162.041,101.07 162.062,100.988 162.095,100.911 162.138,100.84 162.19,100.771 162.247,100.704 162.371,100.566 161.096,100.566 161.219,100.704 161.276,100.771 161.328,100.84 161.371,100.911 161.404,100.988 161.425,101.07 161.431,101.115
  region net $1N38622: 131.945,100.748 132.369,101.172 ccw(c133.324,102.445) 133.324,100.854 132.263,99.793 ccw(c130.672,99.793)
  region net $1N38622: 133.413,98.254 132.813,98.254 ccw(c131.688,98.254) 132.363,99.154 133.863,99.154 ccw(c134.538,98.254)
  region net $1N38620: 134.623,100.61 135.047,101.034 135.081,101.003 135.117,100.975 135.19,100.932 135.268,100.902 135.349,100.882 135.433,100.869 135.521,100.862 135.706,100.852 134.805,99.951 134.795,100.136 134.788,100.224 134.775,100.308 134.755,100.389 134.725,100.467 134.682,100.54 134.654,100.576
  region net $1N38620: 135.953,98.847 135.353,98.847 135.351,98.893 135.345,98.938 135.324,99.02 135.291,99.097 135.248,99.168 135.196,99.237 135.139,99.304 135.016,99.442 136.29,99.442 136.167,99.304 136.11,99.237 136.058,99.168 136.015,99.097 135.982,99.02 135.961,98.938 135.955,98.893
  region net $1N38619: 137.163,100.61 137.587,101.034 137.621,101.003 137.657,100.975 137.73,100.932 137.808,100.902 137.889,100.882 137.973,100.869 138.061,100.862 138.246,100.852 137.345,99.951 137.335,100.136 137.328,100.224 137.315,100.308 137.295,100.389 137.265,100.467 137.222,100.54 137.194,100.576
  region net $1N38619: 138.493,98.847 137.893,98.847 137.891,98.893 137.885,98.938 137.864,99.02 137.831,99.097 137.788,99.168 137.736,99.237 137.679,99.304 137.556,99.442 138.83,99.442 138.707,99.304 138.65,99.237 138.598,99.168 138.555,99.097 138.522,99.02 138.501,98.938 138.495,98.893
  region net $1N38618: 139.703,100.61 140.127,101.034 140.161,101.003 140.197,100.975 140.27,100.932 140.348,100.902 140.429,100.882 140.513,100.869 140.601,100.862 140.786,100.852 139.885,99.951 139.875,100.136 139.868,100.224 139.855,100.308 139.835,100.389 139.805,100.467 139.762,100.54 139.734,100.576
  region net $1N38618: 141.033,98.847 140.433,98.847 140.431,98.893 140.425,98.938 140.404,99.02 140.371,99.097 140.328,99.168 140.276,99.237 140.219,99.304 140.096,99.442 141.37,99.442 141.247,99.304 141.19,99.237 141.138,99.168 141.095,99.097 141.062,99.02 141.041,98.938 141.035,98.893
  region net $1N40669: 127.393,111.928 127.401,112.486 ccw(c128.037,113.335) 128.037,112.274 127.605,111.292 ccw(c126.544,111.292)
  region net $1N40669: 128.155,110.424 127.755,110.424 ccw(c126.48,110.424) 127.605,111.024 128.305,111.024 ccw(c129.43,110.424)
  region net 12V: 99.923,115.804 98.723,115.804 ccw(c96.473,115.804) 97.823,117.604 100.823,117.604 ccw(c102.173,115.804)
  region net 5V: 116.523,117.004 116.123,117.004 ccw(c115.373,117.004) 115.823,117.604 116.823,117.604 ccw(c117.273,117.004)
  region net $1N40669: 141.915,107.856 141.515,107.856 ccw(c140.765,107.856) 141.215,108.456 142.215,108.456 ccw(c142.665,107.856)
  region net D11/PWM: 89.164,101.741 89.128,102.271 ccw(c88.28,102.907) 89.34,102.907 89.801,101.953 ccw(c89.801,100.893)
  region net $1N40669: 93.718,102.271 93.682,101.741 ccw(c93.045,100.893) 93.045,101.953 93.506,102.907 ccw(c94.566,102.907)
  region net $1N40669: 106.122,101.741 106.086,102.271 ccw(c105.237,102.907) 106.298,102.907 106.758,101.953 ccw(c106.758,100.893)
  region net $1N40669: 107.682,103.867 107.718,103.337 ccw(c108.566,102.701) 107.506,102.701 107.045,103.655 ccw(c107.045,104.715)
  region net 5V: 100.682,103.867 100.718,103.337 ccw(c101.566,102.701) 100.506,102.701 100.045,103.655 ccw(c100.045,104.715)
  region net D2/X-STEP: 117.017,90.957 116.734,90.674 116.693,90.721 116.659,90.762 116.64,90.778 116.619,90.791 116.594,90.801 116.563,90.805 116.887,91.129 116.891,91.098 116.9,91.073 116.914,91.052 116.93,91.033 116.971,90.998
  region net D2/X-STEP: 116.147,91.262 116.43,91.545 116.471,91.498 116.506,91.457 116.524,91.441 116.545,91.428 116.571,91.419 116.601,91.414 116.278,91.09 116.273,91.121 116.264,91.146 116.251,91.167 116.234,91.186 116.194,91.221
  region net $1N38622: 147.701,109.504 147.701,110.104 148.067,110.109 148.067,109.499
  region net $1N38622: 148.433,110.104 148.433,109.504 148.067,109.499 148.067,110.109
  region net $1N38622: 147.634,110.104 147.634,109.504 147.268,109.499 147.268,110.109
  region net $1N38620: 147.634,109.104 147.634,108.504 147.268,108.499 147.268,109.109
  region net $1N38620: 148.433,109.104 148.433,108.504 148.067,108.499 148.067,109.109
  region net $1N38620: 147.701,108.504 147.701,109.104 148.067,109.109 148.067,108.499
  region net $1N38619: 147.634,108.104 147.634,107.504 147.268,107.499 147.268,108.109
  region net $1N38619: 148.433,108.104 148.433,107.504 148.067,107.499 148.067,108.109
  region net $1N38619: 147.701,107.504 147.701,108.104 148.067,108.109 148.067,107.499
  region net $1N38618: 147.634,107.104 147.634,106.504 147.268,106.499 147.268,107.109
  region net $1N38618: 147.701,106.504 147.701,107.104 148.067,107.109 148.067,106.499
  region net $1N38618: 148.433,107.104 148.433,106.504 148.067,106.499 148.067,107.109
  region net $1N40669: 147.12,99.856 147.52,99.856 147.516,99.794 147.512,99.741 147.513,99.716 147.519,99.692 147.53,99.668 147.549,99.643 147.091,99.643 147.11,99.668 147.121,99.692 147.127,99.716 147.128,99.741 147.124,99.794
  region net $1N40669: 147.12,100.61 147.52,100.61 147.516,100.548 147.512,100.495 147.513,100.47 147.519,100.446 147.53,100.422 147.549,100.397 147.091,100.397 147.11,100.422 147.121,100.446 147.127,100.47 147.128,100.495 147.124,100.548
  region net $1N40669: 147.52,99.78 147.12,99.78 147.124,99.842 147.128,99.895 147.127,99.92 147.121,99.944 147.11,99.968 147.091,99.993 147.549,99.993 147.53,99.968 147.519,99.944 147.513,99.92 147.512,99.895 147.516,99.842
  region net D3/Y-STEP: 109.918,90.971 109.636,90.689 109.595,90.735 109.56,90.776 109.541,90.792 109.52,90.805 109.495,90.815 109.464,90.819 109.788,91.143 109.792,91.112 109.802,91.087 109.815,91.066 109.831,91.047 109.872,91.012
  region net D3/Y-STEP: 110.631,90.259 110.348,89.976 110.307,90.023 110.272,90.063 110.254,90.08 110.232,90.093 110.207,90.102 110.177,90.107 110.5,90.43 110.505,90.4 110.514,90.375 110.527,90.353 110.544,90.335 110.584,90.3
  region net D3/Y-STEP: 109.761,90.564 110.043,90.846 110.084,90.8 110.119,90.759 110.138,90.743 110.159,90.73 110.184,90.72 110.215,90.716 109.891,90.392 109.887,90.423 109.877,90.448 109.864,90.469 109.848,90.488 109.807,90.523
  region net D2/X-STEP: 116.316,91.658 116.034,91.375 115.993,91.422 115.958,91.463 115.939,91.479 115.918,91.492 115.893,91.501 115.862,91.506 116.186,91.83 116.19,91.799 116.2,91.774 116.213,91.753 116.229,91.734 116.27,91.699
